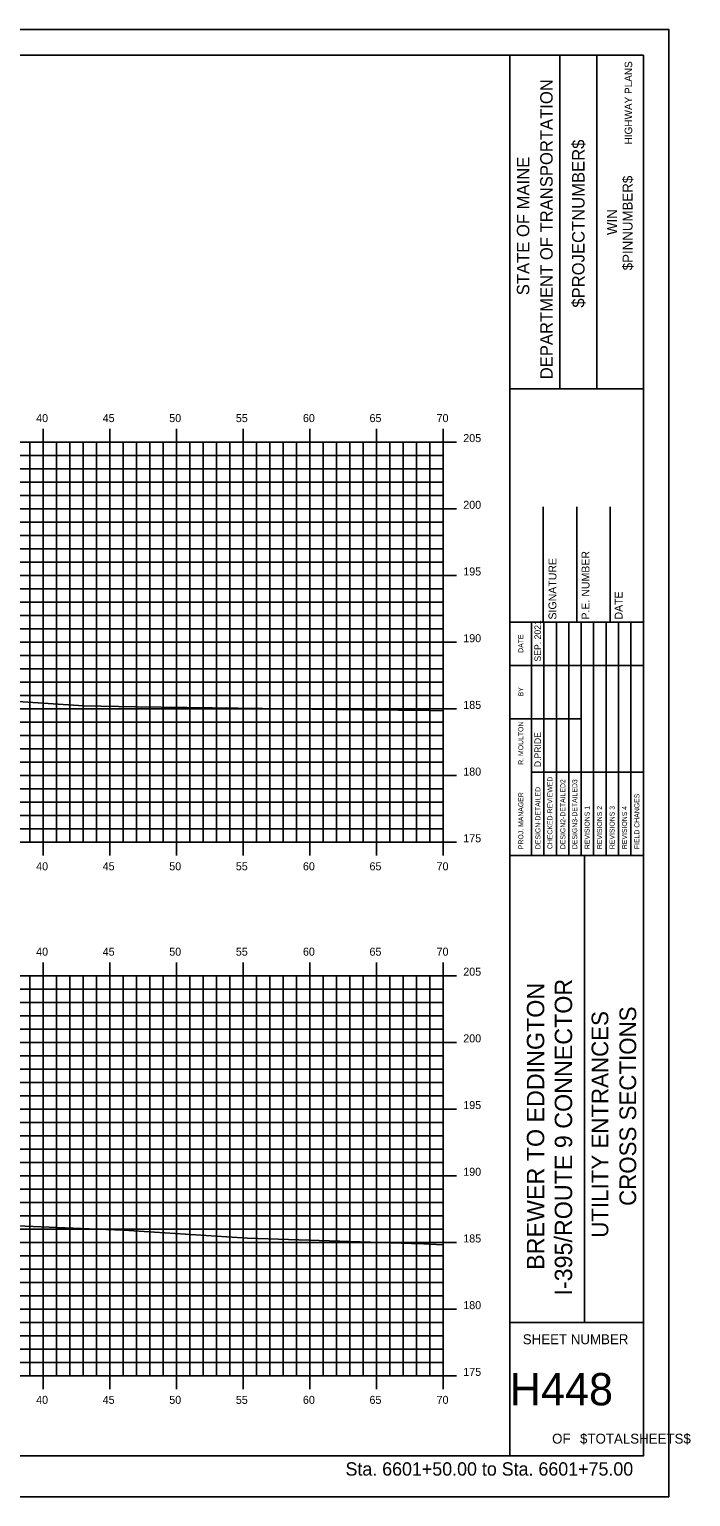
# Model space of a CAD drawing. Extents: x 1723740 to 1723911, y 459560 to 459670.
# Drawn here: x 1723861.7 to 1723911.3, y 459559.6 to 459669.6 of the extents above; entities that cross this region are included whole.
import ezdxf

# ---------------------------------------------------------------- set-up
doc = ezdxf.new("R2010")
doc.units = 0
for name, color, linetype in [('BORDER', 7, 'Continuous'), ('H_V ANNOTATION', 7, 'Continuous'), ('HIGHWAY_TITLE', 7, 'Continuous'), ('MAJOR', 7, 'Continuous'), ('MINOR', 7, 'Continuous'), ('PLOT BOUNDARY', 7, 'Continuous'), ('S_Roadway_Centerline', 7, 'Continuous')]:
    doc.layers.add(name, color=color, linetype=linetype)

msp = doc.modelspace()

# ---------------------------------------------------------------- linework, layer by layer
at = {"layer": 'BORDER'}
for p, q in [((1723897.72, 459562.61), (1723897.72, 459667.61)), ((1723901.45, 459642.61), (1723901.45, 459667.61)), ((1723904.24, 459642.61), (1723904.24, 459667.61)), ((1723897.72, 459642.61), (1723907.72, 459642.61)), ((1723900.22, 459625.12), (1723900.22, 459633.76)), ((1723902.72, 459625.12), (1723902.72, 459633.76)), ((1723905.22, 459625.12), (1723905.22, 459633.76)), ((1723897.72, 459625.12), (1723907.72, 459625.12)), ((1723897.72, 459607.62), (1723907.72, 459607.62)), ((1723903.31, 459572.62), (1723903.31, 459607.62)), ((1723897.72, 459572.62), (1723907.72, 459572.62))]:
    msp.add_line(p, q, dxfattribs=at)
msp.add_lwpolyline([(1723747.72, 459562.61), (1723907.72, 459562.61), (1723907.72, 459667.61), (1723747.72, 459667.61)], close=True, dxfattribs=at)
for points in [[(1723899.33, 459621.87), (1723899.33, 459625.12)], [(1723900.26, 459607.62), (1723900.26, 459625.12)], [(1723901.2, 459625.12), (1723901.2, 459607.62)], [(1723902.13, 459607.62), (1723902.13, 459625.12)], [(1723903.06, 459607.62), (1723903.06, 459625.12)], [(1723903.99, 459607.62), (1723903.99, 459625.12)], [(1723904.92, 459607.62), (1723904.92, 459625.12)], [(1723905.85, 459607.62), (1723905.85, 459625.12)], [(1723906.79, 459607.62), (1723906.79, 459625.12)], [(1723899.33, 459607.62), (1723899.33, 459624.41)], [(1723897.72, 459621.87), (1723907.72, 459621.87)], [(1723897.72, 459617.87), (1723899.33, 459617.87)], [(1723899.33, 459617.87), (1723903.06, 459617.87)], [(1723899.33, 459613.87), (1723907.72, 459613.87)]]:
    msp.add_lwpolyline(points, dxfattribs=at)
at = {"layer": 'MAJOR'}
for p, q in [((1723862.72, 459639.61), (1723862.72, 459638.61)), ((1723867.72, 459639.61), (1723867.72, 459638.61)), ((1723872.72, 459639.61), (1723872.72, 459638.61)), ((1723877.72, 459639.61), (1723877.72, 459638.61)), ((1723882.72, 459639.61), (1723882.72, 459638.61)), ((1723887.72, 459639.61), (1723887.72, 459638.61)), ((1723892.72, 459639.61), (1723892.72, 459638.61)), ((1723752.72, 459638.61), (1723892.72, 459638.61)), ((1723752.72, 459638.61), (1723892.72, 459638.61)), ((1723862.72, 459608.61), (1723862.72, 459638.61)), ((1723867.72, 459608.61), (1723867.72, 459638.61)), ((1723872.72, 459608.61), (1723872.72, 459638.61)), ((1723877.72, 459608.61), (1723877.72, 459638.61)), ((1723882.72, 459608.61), (1723882.72, 459638.61)), ((1723887.72, 459608.61), (1723887.72, 459638.61)), ((1723893.72, 459638.61), (1723891.71, 459638.61)), ((1723892.72, 459608.61), (1723892.72, 459638.61)), ((1723892.72, 459608.61), (1723892.72, 459638.61)), ((1723752.72, 459633.61), (1723892.72, 459633.61)), ((1723893.72, 459633.61), (1723891.71, 459633.61)), ((1723752.72, 459628.61), (1723892.72, 459628.61)), ((1723893.72, 459628.61), (1723891.71, 459628.61)), ((1723752.72, 459623.61), (1723892.72, 459623.61)), ((1723893.72, 459623.61), (1723891.71, 459623.61)), ((1723752.72, 459618.61), (1723892.72, 459618.61)), ((1723893.72, 459618.61), (1723891.71, 459618.61)), ((1723752.72, 459613.61), (1723892.72, 459613.61)), ((1723893.72, 459613.61), (1723891.71, 459613.61)), ((1723752.72, 459608.61), (1723892.72, 459608.61)), ((1723752.72, 459608.61), (1723892.72, 459608.61)), ((1723862.72, 459607.61), (1723862.72, 459608.61)), ((1723867.72, 459607.61), (1723867.72, 459608.61)), ((1723872.72, 459607.61), (1723872.72, 459608.61)), ((1723877.72, 459607.61), (1723877.72, 459608.61)), ((1723882.72, 459607.61), (1723882.72, 459608.61)), ((1723887.72, 459607.61), (1723887.72, 459608.61)), ((1723893.72, 459608.61), (1723891.71, 459608.61)), ((1723892.72, 459607.61), (1723892.72, 459608.61)), ((1723862.72, 459599.61), (1723862.72, 459598.61)), ((1723867.72, 459599.61), (1723867.72, 459598.61)), ((1723872.72, 459599.61), (1723872.72, 459598.61)), ((1723877.72, 459599.61), (1723877.72, 459598.61)), ((1723882.72, 459599.61), (1723882.72, 459598.61)), ((1723887.72, 459599.61), (1723887.72, 459598.61)), ((1723892.72, 459599.61), (1723892.72, 459598.61)), ((1723752.72, 459598.61), (1723892.72, 459598.61)), ((1723752.72, 459598.61), (1723892.72, 459598.61)), ((1723862.72, 459568.61), (1723862.72, 459598.61)), ((1723867.72, 459568.61), (1723867.72, 459598.61)), ((1723872.72, 459568.61), (1723872.72, 459598.61)), ((1723877.72, 459568.61), (1723877.72, 459598.61)), ((1723882.72, 459568.61), (1723882.72, 459598.61)), ((1723887.72, 459568.61), (1723887.72, 459598.61)), ((1723893.72, 459598.61), (1723891.71, 459598.61)), ((1723892.72, 459568.61), (1723892.72, 459598.61)), ((1723892.72, 459568.61), (1723892.72, 459598.61)), ((1723752.72, 459593.61), (1723892.72, 459593.61)), ((1723893.72, 459593.61), (1723891.71, 459593.61)), ((1723752.72, 459588.61), (1723892.72, 459588.61)), ((1723893.72, 459588.61), (1723891.71, 459588.61)), ((1723752.72, 459583.61), (1723892.72, 459583.61)), ((1723893.72, 459583.61), (1723891.71, 459583.61)), ((1723752.72, 459578.61), (1723892.72, 459578.61)), ((1723893.72, 459578.61), (1723891.71, 459578.61)), ((1723752.72, 459573.61), (1723892.72, 459573.61)), ((1723893.72, 459573.61), (1723891.71, 459573.61)), ((1723752.72, 459568.61), (1723892.72, 459568.61)), ((1723752.72, 459568.61), (1723892.72, 459568.61)), ((1723862.72, 459567.61), (1723862.72, 459568.61)), ((1723867.72, 459567.61), (1723867.72, 459568.61)), ((1723872.72, 459567.61), (1723872.72, 459568.61)), ((1723877.72, 459567.61), (1723877.72, 459568.61)), ((1723882.72, 459567.61), (1723882.72, 459568.61)), ((1723887.72, 459567.61), (1723887.72, 459568.61)), ((1723893.72, 459568.61), (1723891.71, 459568.61)), ((1723892.72, 459567.61), (1723892.72, 459568.61))]:
    msp.add_line(p, q, dxfattribs=at)
at = {"layer": 'MINOR'}
for p, q in [((1723861.72, 459608.61), (1723861.72, 459638.61)), ((1723863.72, 459608.61), (1723863.72, 459638.61)), ((1723864.72, 459608.61), (1723864.72, 459638.61)), ((1723865.72, 459608.61), (1723865.72, 459638.61)), ((1723866.72, 459608.61), (1723866.72, 459638.61)), ((1723868.72, 459608.61), (1723868.72, 459638.61)), ((1723869.72, 459608.61), (1723869.72, 459638.61)), ((1723870.72, 459608.61), (1723870.72, 459638.61)), ((1723871.72, 459608.61), (1723871.72, 459638.61)), ((1723873.72, 459608.61), (1723873.72, 459638.61)), ((1723874.72, 459608.61), (1723874.72, 459638.61)), ((1723875.72, 459608.61), (1723875.72, 459638.61)), ((1723876.72, 459608.61), (1723876.72, 459638.61)), ((1723878.72, 459608.61), (1723878.72, 459638.61)), ((1723879.72, 459608.61), (1723879.72, 459638.61)), ((1723880.72, 459608.61), (1723880.72, 459638.61)), ((1723881.72, 459608.61), (1723881.72, 459638.61)), ((1723883.72, 459608.61), (1723883.72, 459638.61)), ((1723884.72, 459608.61), (1723884.72, 459638.61)), ((1723885.72, 459608.61), (1723885.72, 459638.61)), ((1723886.72, 459608.61), (1723886.72, 459638.61)), ((1723888.72, 459608.61), (1723888.72, 459638.61)), ((1723889.72, 459608.61), (1723889.72, 459638.61)), ((1723890.72, 459608.61), (1723890.72, 459638.61)), ((1723891.72, 459608.61), (1723891.72, 459638.61)), ((1723752.72, 459637.61), (1723892.72, 459637.61)), ((1723892.72, 459637.61), (1723891.71, 459637.61)), ((1723752.72, 459636.61), (1723892.72, 459636.61)), ((1723892.72, 459636.61), (1723891.71, 459636.61)), ((1723752.72, 459635.61), (1723892.72, 459635.61)), ((1723892.72, 459635.61), (1723891.71, 459635.61)), ((1723752.72, 459634.61), (1723892.72, 459634.61)), ((1723892.72, 459634.61), (1723891.71, 459634.61)), ((1723752.72, 459632.61), (1723892.72, 459632.61)), ((1723892.72, 459632.61), (1723891.71, 459632.61)), ((1723752.72, 459631.61), (1723892.72, 459631.61)), ((1723752.72, 459630.61), (1723892.72, 459630.61)), ((1723892.72, 459631.61), (1723891.71, 459631.61)), ((1723892.72, 459630.61), (1723891.71, 459630.61)), ((1723752.72, 459629.61), (1723892.72, 459629.61)), ((1723892.72, 459629.61), (1723891.71, 459629.61)), ((1723752.72, 459627.61), (1723892.72, 459627.61)), ((1723892.72, 459627.61), (1723891.71, 459627.61)), ((1723752.72, 459626.61), (1723892.72, 459626.61)), ((1723892.72, 459626.61), (1723891.71, 459626.61)), ((1723752.72, 459625.61), (1723892.72, 459625.61)), ((1723892.72, 459625.61), (1723891.71, 459625.61)), ((1723752.72, 459624.61), (1723892.72, 459624.61)), ((1723892.72, 459624.61), (1723891.71, 459624.61)), ((1723752.72, 459622.61), (1723892.72, 459622.61)), ((1723892.72, 459622.61), (1723891.71, 459622.61)), ((1723752.72, 459621.61), (1723892.72, 459621.61)), ((1723892.72, 459621.61), (1723891.71, 459621.61)), ((1723752.72, 459620.61), (1723892.72, 459620.61)), ((1723752.72, 459619.61), (1723892.72, 459619.61)), ((1723892.72, 459620.61), (1723891.71, 459620.61)), ((1723892.72, 459619.61), (1723891.71, 459619.61)), ((1723752.72, 459617.61), (1723892.72, 459617.61)), ((1723892.72, 459617.61), (1723891.71, 459617.61)), ((1723752.72, 459616.61), (1723892.72, 459616.61)), ((1723892.72, 459616.61), (1723891.71, 459616.61)), ((1723752.72, 459615.61), (1723892.72, 459615.61)), ((1723892.72, 459615.61), (1723891.71, 459615.61)), ((1723752.72, 459614.61), (1723892.72, 459614.61)), ((1723892.72, 459614.61), (1723891.71, 459614.61)), ((1723752.72, 459612.61), (1723892.72, 459612.61)), ((1723892.72, 459612.61), (1723891.71, 459612.61)), ((1723752.72, 459611.61), (1723892.72, 459611.61)), ((1723892.72, 459611.61), (1723891.71, 459611.61)), ((1723752.72, 459610.61), (1723892.72, 459610.61)), ((1723892.72, 459610.61), (1723891.71, 459610.61)), ((1723752.72, 459609.61), (1723892.72, 459609.61)), ((1723892.72, 459609.61), (1723891.71, 459609.61)), ((1723752.72, 459597.61), (1723892.72, 459597.61)), ((1723861.72, 459568.61), (1723861.72, 459598.61)), ((1723863.72, 459568.61), (1723863.72, 459598.61)), ((1723864.72, 459568.61), (1723864.72, 459598.61)), ((1723865.72, 459568.61), (1723865.72, 459598.61)), ((1723866.72, 459568.61), (1723866.72, 459598.61)), ((1723868.72, 459568.61), (1723868.72, 459598.61)), ((1723869.72, 459568.61), (1723869.72, 459598.61)), ((1723870.72, 459568.61), (1723870.72, 459598.61)), ((1723871.72, 459568.61), (1723871.72, 459598.61)), ((1723873.72, 459568.61), (1723873.72, 459598.61)), ((1723874.72, 459568.61), (1723874.72, 459598.61)), ((1723875.72, 459568.61), (1723875.72, 459598.61)), ((1723876.72, 459568.61), (1723876.72, 459598.61)), ((1723878.72, 459568.61), (1723878.72, 459598.61)), ((1723879.72, 459568.61), (1723879.72, 459598.61)), ((1723880.72, 459568.61), (1723880.72, 459598.61)), ((1723881.72, 459568.61), (1723881.72, 459598.61)), ((1723883.72, 459568.61), (1723883.72, 459598.61)), ((1723884.72, 459568.61), (1723884.72, 459598.61)), ((1723885.72, 459568.61), (1723885.72, 459598.61)), ((1723886.72, 459568.61), (1723886.72, 459598.61)), ((1723888.72, 459568.61), (1723888.72, 459598.61)), ((1723889.72, 459568.61), (1723889.72, 459598.61)), ((1723890.72, 459568.61), (1723890.72, 459598.61)), ((1723892.72, 459597.61), (1723891.71, 459597.61)), ((1723891.72, 459568.61), (1723891.72, 459598.61)), ((1723752.72, 459596.61), (1723892.72, 459596.61)), ((1723892.72, 459596.61), (1723891.71, 459596.61)), ((1723752.72, 459595.61), (1723892.72, 459595.61)), ((1723892.72, 459595.61), (1723891.71, 459595.61)), ((1723752.72, 459594.61), (1723892.72, 459594.61)), ((1723892.72, 459594.61), (1723891.71, 459594.61)), ((1723752.72, 459592.61), (1723892.72, 459592.61)), ((1723892.72, 459592.61), (1723891.71, 459592.61)), ((1723752.72, 459591.61), (1723892.72, 459591.61)), ((1723892.72, 459591.61), (1723891.71, 459591.61)), ((1723752.72, 459590.61), (1723892.72, 459590.61)), ((1723892.72, 459590.61), (1723891.71, 459590.61)), ((1723752.72, 459589.61), (1723892.72, 459589.61)), ((1723892.72, 459589.61), (1723891.71, 459589.61)), ((1723752.72, 459587.61), (1723892.72, 459587.61)), ((1723752.72, 459586.61), (1723892.72, 459586.61)), ((1723892.72, 459587.61), (1723891.71, 459587.61)), ((1723892.72, 459586.61), (1723891.71, 459586.61)), ((1723752.72, 459585.61), (1723892.72, 459585.61)), ((1723892.72, 459585.61), (1723891.71, 459585.61)), ((1723752.72, 459584.61), (1723892.72, 459584.61)), ((1723892.72, 459584.61), (1723891.71, 459584.61)), ((1723752.72, 459582.61), (1723892.72, 459582.61)), ((1723892.72, 459582.61), (1723891.71, 459582.61)), ((1723752.72, 459581.61), (1723892.72, 459581.61)), ((1723892.72, 459581.61), (1723891.71, 459581.61)), ((1723752.72, 459580.61), (1723892.72, 459580.61)), ((1723892.72, 459580.61), (1723891.71, 459580.61)), ((1723752.72, 459579.61), (1723892.72, 459579.61)), ((1723892.72, 459579.61), (1723891.71, 459579.61)), ((1723752.72, 459577.61), (1723892.72, 459577.61)), ((1723892.72, 459577.61), (1723891.71, 459577.61)), ((1723752.72, 459576.61), (1723892.72, 459576.61)), ((1723752.72, 459575.61), (1723892.72, 459575.61)), ((1723892.72, 459576.61), (1723891.71, 459576.61)), ((1723892.72, 459575.61), (1723891.71, 459575.61)), ((1723752.72, 459574.61), (1723892.72, 459574.61)), ((1723892.72, 459574.61), (1723891.71, 459574.61)), ((1723752.72, 459572.61), (1723892.72, 459572.61)), ((1723892.72, 459572.61), (1723891.71, 459572.61)), ((1723752.72, 459571.61), (1723892.72, 459571.61)), ((1723892.72, 459571.61), (1723891.71, 459571.61)), ((1723752.72, 459570.61), (1723892.72, 459570.61)), ((1723892.72, 459570.61), (1723891.71, 459570.61)), ((1723752.72, 459569.61), (1723892.72, 459569.61)), ((1723892.72, 459569.61), (1723891.71, 459569.61))]:
    msp.add_line(p, q, dxfattribs=at)
at = {"layer": 'PLOT BOUNDARY'}
msp.add_lwpolyline([(1723739.62, 459559.55), (1723909.62, 459559.55), (1723909.62, 459669.55), (1723739.62, 459669.55)], close=True, dxfattribs=at)
at = {"layer": 'S_Roadway_Centerline'}
for points in [[(1723752.72, 459622.54), (1723759.22, 459622.29), (1723760.58, 459622.19), (1723762.62, 459622.14), (1723773.54, 459621.89), (1723782.14, 459621.6), (1723787.53, 459621.52), (1723807.19, 459620.76), (1723811.22, 459620.55), (1723825.57, 459620.18), (1723836.05, 459620), (1723846.28, 459619.83), (1723860.82, 459619.16), (1723865.74, 459618.85), (1723869.67, 459618.76), (1723877.33, 459618.67), (1723886.57, 459618.54), (1723889.34, 459618.52), (1723891.65, 459618.48), (1723892.72, 459618.47)], [(1723752.72, 459582.84), (1723758.56, 459582.38), (1723762.18, 459582.27), (1723766.71, 459582.17), (1723774.4, 459582.14), (1723791, 459582.02), (1723802.91, 459581.73), (1723808.36, 459581.53), (1723813.88, 459581.43), (1723819.34, 459581.21), (1723825.09, 459580.85), (1723832.69, 459580.38), (1723841.04, 459580.51), (1723843.4, 459580.59), (1723845.73, 459580.48), (1723866.78, 459579.6), (1723868.76, 459579.54), (1723878.05, 459578.92), (1723890.34, 459578.54), (1723890.75, 459578.53), (1723892.72, 459578.43)]]:
    msp.add_lwpolyline(points, dxfattribs=at)

# ---------------------------------------------------------------- texts
at = {"layer": 'BORDER'}
for s, height, p in [('DEPARTMENT OF TRANSPORTATION', 0.9318, (1723900.92, 459643.32)), ('$PROJECTNUMBER$', 0.9318, (1723903.31, 459648.69)), ('STATE OF MAINE', 0.9318, (1723899.17, 459649.62)), ('$PINNUMBER$', 0.7453, (1723906.91, 459651.49)), ('WIN', 0.745, (1723905.75, 459654.14)), ('SIGNATURE', 0.591, (1723901.2, 459625.31)), ('P.E. NUMBER', 0.5906, (1723903.68, 459625.31)), ('DATE', 0.591, (1723906.16, 459625.31)), ('SEP. 2021', 0.485, (1723900.04, 459622.16)), ('DATE', 0.371, (1723898.72, 459622.82)), ('BY', 0.371, (1723898.72, 459619.55)), ('R. MOULTON', 0.373, (1723898.72, 459614.42)), ('D.PRIDE', 0.485, (1723900.04, 459614.24)), ('CHECKED-REVIEWED', 0.3727, (1723900.9, 459608.1)), ('DESIGN2-DETAILED2', 0.3727, (1723901.87, 459608.1)), ('DESIGN3-DETAILED3', 0.3727, (1723902.76, 459608.1)), ('PROJ. MANAGER', 0.3727, (1723898.72, 459608.1)), ('DESIGN-DETAILED', 0.3727, (1723900, 459608.1)), ('FIELD CHANGES', 0.3727, (1723907.42, 459608.1)), ('REVISIONS 1', 0.3727, (1723903.69, 459608.1)), ('REVISIONS 2', 0.3727, (1723904.62, 459608.1)), ('REVISIONS 3', 0.3727, (1723905.56, 459608.1)), ('REVISIONS 4', 0.3727, (1723906.49, 459608.1)), ('UTILITY ENTRANCES', 1.25, (1723905.09, 459578.96)), ('CROSS SECTIONS', 1.25, (1723907.18, 459581.35))]:
    msp.add_text(s, height=height, rotation=90, dxfattribs=at).set_placement(p)
for s, height, p in [('SHEET NUMBER', 0.7453, (1723898.68, 459570.98)), ('H448', 2.419, (1723897.71, 459566.4)), ('OF', 0.745, (1723900.88, 459563.53)), ('$TOTALSHEETS$', 0.7453, (1723902.97, 459563.53))]:
    msp.add_text(s, height=height, dxfattribs=at).set_placement(p)
at = {"layer": 'H_V ANNOTATION'}
for s, height, p in [('40', 0.6, (1723862.2, 459640.11)), ('45', 0.6, (1723867.19, 459640.11)), ('50', 0.6, (1723872.18, 459640.11)), ('55', 0.6, (1723877.17, 459640.11)), ('60', 0.6, (1723882.2, 459640.11)), ('65', 0.6, (1723887.19, 459640.11)), ('70', 0.6, (1723892.22, 459640.11)), ('205', 0.6, (1723894.22, 459638.61)), ('200', 0.6, (1723894.22, 459633.61)), ('195', 0.6, (1723894.22, 459628.61)), ('190', 0.6, (1723894.22, 459623.61)), ('185', 0.6, (1723894.22, 459618.61)), ('180', 0.6, (1723894.22, 459613.61)), ('175', 0.6, (1723894.22, 459608.61)), ('40', 0.6, (1723862.2, 459606.51)), ('45', 0.6, (1723867.19, 459606.51)), ('50', 0.6, (1723872.18, 459606.51)), ('55', 0.6, (1723877.17, 459606.51)), ('60', 0.6, (1723882.2, 459606.51)), ('65', 0.6, (1723887.19, 459606.51)), ('70', 0.6, (1723892.22, 459606.51)), ('40', 0.6, (1723862.2, 459600.11)), ('45', 0.6, (1723867.19, 459600.11)), ('50', 0.6, (1723872.18, 459600.11)), ('55', 0.6, (1723877.17, 459600.11)), ('60', 0.6, (1723882.2, 459600.11)), ('65', 0.6, (1723887.19, 459600.11)), ('70', 0.6, (1723892.22, 459600.11)), ('205', 0.6, (1723894.22, 459598.61)), ('200', 0.6, (1723894.22, 459593.61)), ('195', 0.6, (1723894.22, 459588.61)), ('190', 0.6, (1723894.22, 459583.61)), ('185', 0.6, (1723894.22, 459578.61)), ('180', 0.6, (1723894.22, 459573.61)), ('175', 0.6, (1723894.22, 459568.61)), ('40', 0.6, (1723862.2, 459566.51)), ('45', 0.6, (1723867.19, 459566.51)), ('50', 0.6, (1723872.18, 459566.51)), ('55', 0.6, (1723877.17, 459566.51)), ('60', 0.6, (1723882.2, 459566.51)), ('65', 0.6, (1723887.19, 459566.51)), ('70', 0.6, (1723892.22, 459566.51)), ('Sta. 6601+50.00 to Sta. 6601+75.00', 1.0002, (1723885.39, 459561.13))]:
    msp.add_text(s, height=height, dxfattribs=at).set_placement(p)
at = {"layer": 'HIGHWAY_TITLE'}
for s, height, p in [('HIGHWAY PLANS', 0.559, (1723906.88, 459660.93)), ('BREWER TO EDDINGTON', 1.3043, (1723900.29, 459576.56)), ('I-395/ROUTE 9 CONNECTOR', 1.3043, (1723902.38, 459574.63))]:
    msp.add_text(s, height=height, rotation=90, dxfattribs=at).set_placement(p)

doc.saveas('drawing.dxf')
